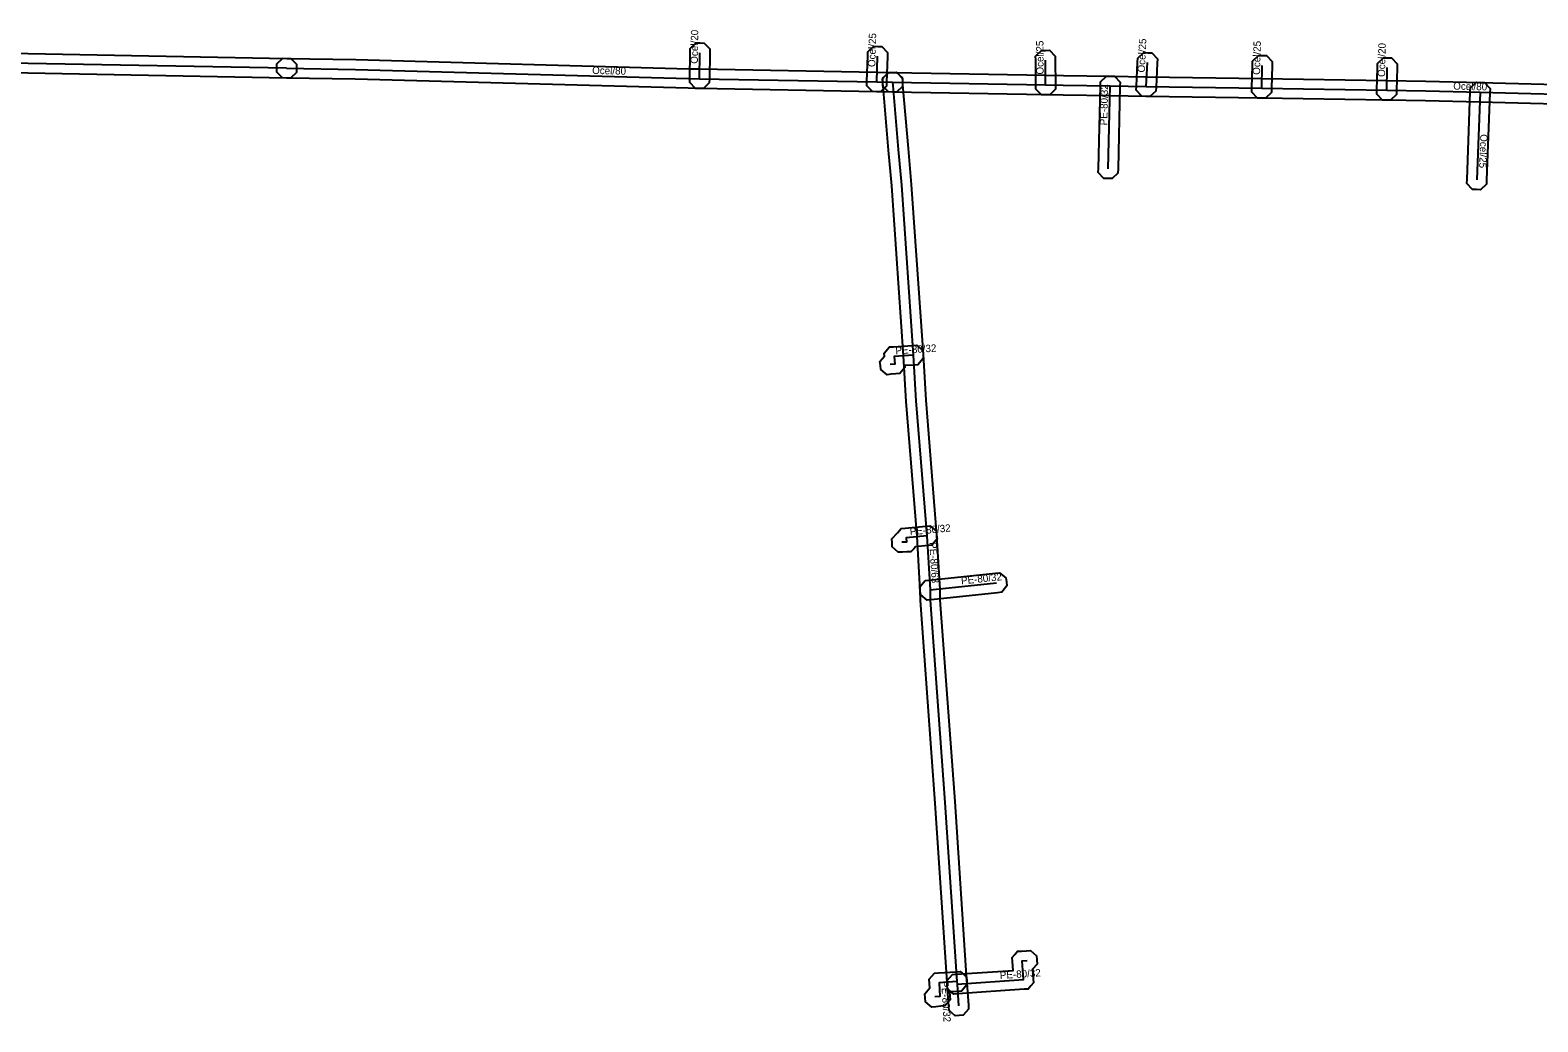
# Model space of a CAD drawing. Extents: x -569373 to -565022, y -1135090 to -1131496.
# Drawn here: x -565577.8 to -565424.2, y -1133558 to -1133457 of the extents above; entities that cross this region are included whole.
import ezdxf

# ---------------------------------------------------------------- set-up
doc = ezdxf.new("R2010")
doc.units = 0
for name, color, linetype in [('1', 7, 'Continuous'), ('24', 7, 'Continuous'), ('30', 7, 'Continuous')]:
    doc.layers.add(name, color=color, linetype=linetype)

msp = doc.modelspace()

# ---------------------------------------------------------------- linework, layer by layer
at = {"layer": '1'}
for points in [[(-565551.275, -1133461.887), (-565551.689, -1133461.88), (-565578.038, -1133461.39), (-565632.147, -1133460.49), (-565632.561, -1133460.483), (-565633.137, -1133459.887), (-565633.13, -1133459.473), (-565633.123, -1133459.059), (-565632.527, -1133458.483), (-565632.113, -1133458.49), (-565578.002, -1133459.39), (-565551.651, -1133459.88), (-565551.237, -1133459.888), (-565550.663, -1133460.485), (-565550.67, -1133460.899), (-565550.678, -1133461.313)], [(-565510.596, -1133462.349), (-565510.59, -1133461.935), (-565510.55, -1133459.295), (-565510.544, -1133458.881), (-565509.949, -1133458.304), (-565509.535, -1133458.31), (-565509.121, -1133458.316), (-565508.544, -1133458.911), (-565508.55, -1133459.325), (-565508.59, -1133461.965), (-565508.596, -1133462.379), (-565509.191, -1133462.956), (-565509.605, -1133462.95), (-565510.019, -1133462.944)], [(-565492.542, -1133462.663), (-565492.53, -1133462.249), (-565492.45, -1133459.629), (-565492.437, -1133459.215), (-565491.833, -1133458.648), (-565491.419, -1133458.66), (-565491.005, -1133458.673), (-565490.438, -1133459.277), (-565490.45, -1133459.691), (-565490.53, -1133462.311), (-565490.543, -1133462.725), (-565491.147, -1133463.292), (-565491.561, -1133463.28), (-565491.975, -1133463.267)], [(-565475.328, -1133463.008), (-565475.33, -1133462.594), (-565475.34, -1133460.064), (-565475.342, -1133459.65), (-565474.758, -1133459.062), (-565474.344, -1133459.06), (-565473.93, -1133459.058), (-565473.342, -1133459.642), (-565473.34, -1133460.056), (-565473.33, -1133462.586), (-565473.328, -1133463), (-565473.912, -1133463.588), (-565474.326, -1133463.59), (-565474.74, -1133463.592)], [(-565465.088, -1133463.119), (-565465.069, -1133462.705), (-565464.959, -1133460.265), (-565464.94, -1133459.851), (-565464.329, -1133459.292), (-565463.915, -1133459.311), (-565463.501, -1133459.33), (-565462.942, -1133459.941), (-565462.961, -1133460.355), (-565463.071, -1133462.795), (-565463.09, -1133463.209), (-565463.701, -1133463.768), (-565464.115, -1133463.749), (-565464.529, -1133463.73)], [(-565552.067, -1133459.873), (-565551.653, -1133459.88), (-565544.628, -1133460), (-565510.697, -1133460.93), (-565509.572, -1133460.95), (-565491.512, -1133461.28), (-565489.901, -1133461.31), (-565489.487, -1133461.318), (-565488.913, -1133461.915), (-565488.92, -1133462.329), (-565488.928, -1133462.743), (-565489.525, -1133463.317), (-565489.939, -1133463.31), (-565491.548, -1133463.28), (-565509.608, -1133462.95), (-565510.743, -1133462.93), (-565544.672, -1133462), (-565551.687, -1133461.88), (-565552.101, -1133461.873), (-565552.677, -1133461.277), (-565552.67, -1133460.863), (-565552.663, -1133460.449)], [(-565453.32, -1133463.318), (-565453.31, -1133462.904), (-565453.25, -1133460.564), (-565453.239, -1133460.15), (-565452.638, -1133459.58), (-565452.224, -1133459.59), (-565451.81, -1133459.601), (-565451.24, -1133460.202), (-565451.25, -1133460.616), (-565451.31, -1133462.956), (-565451.321, -1133463.37), (-565451.922, -1133463.94), (-565452.336, -1133463.93), (-565452.75, -1133463.919)], [(-565440.579, -1133463.522), (-565440.57, -1133463.108), (-565440.52, -1133460.798), (-565440.511, -1133460.384), (-565439.912, -1133459.811), (-565439.498, -1133459.82), (-565439.084, -1133459.829), (-565438.511, -1133460.428), (-565438.52, -1133460.842), (-565438.57, -1133463.152), (-565438.579, -1133463.566), (-565439.178, -1133464.139), (-565439.592, -1133464.13), (-565440.006, -1133464.121)], [(-565488.946, -1133461.838), (-565488.922, -1133462.251), (-565488.903, -1133462.578), (-565488.344, -1133469.062), (-565488.013, -1133472.721), (-565486.822, -1133490.056), (-565486.542, -1133494.7), (-565485.432, -1133508.45), (-565485.1, -1133513.995), (-565485.09, -1133515.039), (-565483.592, -1133535.6), (-565482.373, -1133553.857), (-565482.353, -1133554.106), (-565482.202, -1133556.322), (-565482.174, -1133556.735), (-565482.719, -1133557.36), (-565483.132, -1133557.388), (-565483.545, -1133557.416), (-565484.17, -1133556.871), (-565484.198, -1133556.458), (-565484.347, -1133554.254), (-565484.367, -1133554.003), (-565485.588, -1133535.74), (-565487.09, -1133515.121), (-565487.1, -1133514.065), (-565487.428, -1133508.59), (-565488.538, -1133494.84), (-565488.818, -1133490.184), (-565490.007, -1133472.879), (-565490.336, -1133469.238), (-565490.897, -1133462.722), (-565490.918, -1133462.369), (-565490.942, -1133461.955), (-565490.392, -1133461.336), (-565489.979, -1133461.312), (-565489.565, -1133461.288)], [(-565468.96, -1133471.51), (-565468.95, -1133471.096), (-565468.75, -1133462.666), (-565468.74, -1133462.252), (-565468.14, -1133461.68), (-565467.726, -1133461.69), (-565467.312, -1133461.7), (-565466.74, -1133462.3), (-565466.75, -1133462.714), (-565466.95, -1133471.144), (-565466.96, -1133471.558), (-565467.56, -1133472.13), (-565467.974, -1133472.12), (-565468.388, -1133472.11)], [(-565429.046, -1133462.953), (-565429.061, -1133463.367), (-565429.391, -1133472.287), (-565429.406, -1133472.701), (-565430.013, -1133473.264), (-565430.427, -1133473.249), (-565430.841, -1133473.234), (-565431.404, -1133472.627), (-565431.389, -1133472.213), (-565431.059, -1133463.293), (-565431.044, -1133462.879), (-565430.437, -1133462.316), (-565430.023, -1133462.331), (-565429.609, -1133462.346)], [(-565491.208, -1133490.764), (-565490.755, -1133490.203), (-565490.775, -1133489.902), (-565490.23, -1133489.28), (-565489.817, -1133489.252), (-565487.887, -1133489.122), (-565487.474, -1133489.094), (-565486.85, -1133489.64), (-565486.822, -1133490.053), (-565486.794, -1133490.466), (-565487.34, -1133491.09), (-565487.753, -1133491.118), (-565488.687, -1133491.181), (-565488.676, -1133491.357), (-565489.194, -1133491.972), (-565489.594, -1133492.014), (-565490.064, -1133492.064), (-565490.476, -1133492.108), (-565491.121, -1133491.588), (-565491.164, -1133491.176)], [(-565489.427, -1133508.199), (-565489.41, -1133508.198), (-565489.039, -1133507.762), (-565488.634, -1133507.724), (-565486.524, -1133507.524), (-565486.112, -1133507.485), (-565485.473, -1133508.013), (-565485.434, -1133508.426), (-565485.395, -1133508.838), (-565485.923, -1133509.477), (-565486.336, -1133509.516), (-565487.594, -1133509.635), (-565487.765, -1133509.827), (-565488.046, -1133510.141), (-565488.467, -1133510.159), (-565488.927, -1133510.179), (-565489.341, -1133510.197), (-565489.951, -1133509.637), (-565489.969, -1133509.223), (-565489.987, -1133508.809)], [(-565486.616, -1133513.078), (-565486.204, -1133513.035), (-565479.424, -1133512.325), (-565479.012, -1133512.282), (-565478.368, -1133512.804), (-565478.325, -1133513.216), (-565478.282, -1133513.628), (-565478.804, -1133514.272), (-565479.216, -1133514.315), (-565485.996, -1133515.025), (-565486.408, -1133515.068), (-565487.052, -1133514.546), (-565487.095, -1133514.134), (-565487.138, -1133513.722)], [(-565475.197, -1133552.142), (-565475.65, -1133552.655), (-565475.582, -1133553.652), (-565475.554, -1133554.065), (-565475.826, -1133554.377), (-565476.099, -1133554.69), (-565476.512, -1133554.718), (-565483.282, -1133555.178), (-565483.695, -1133555.206), (-565484.32, -1133554.661), (-565484.348, -1133554.248), (-565484.376, -1133553.835), (-565483.831, -1133553.21), (-565483.418, -1133553.182), (-565477.646, -1133552.79), (-565477.708, -1133551.888), (-565477.736, -1133551.473), (-565477.461, -1133551.16), (-565477.187, -1133550.847), (-565476.771, -1133550.822), (-565476.281, -1133550.792), (-565475.868, -1133550.767), (-565475.247, -1133551.316), (-565475.222, -1133551.729)], [(-565486.645, -1133555.173), (-565486.142, -1133554.563), (-565486.168, -1133554.107), (-565486.192, -1133553.696), (-565485.647, -1133553.079), (-565485.237, -1133553.052), (-565483.437, -1133552.932), (-565483.024, -1133552.905), (-565482.4, -1133553.45), (-565482.372, -1133553.863), (-565482.345, -1133554.276), (-565482.89, -1133554.9), (-565483.303, -1133554.928), (-565484.115, -1133554.982), (-565484.092, -1133555.383), (-565484.069, -1133555.785), (-565484.593, -1133556.396), (-565484.994, -1133556.435), (-565485.514, -1133556.485), (-565485.927, -1133556.525), (-565486.566, -1133555.998), (-565486.605, -1133555.586)]]:
    msp.add_lwpolyline(points, close=True, dxfattribs=at)
msp.add_lwpolyline([(-565417.126, -1133464.67), (-565430.086, -1133464.33), (-565435.61, -1133464.19), (-565439.585, -1133464.13), (-565452.326, -1133463.93), (-565464.086, -1133463.75), (-565467.765, -1133463.69), (-565472.546, -1133463.62), (-565474.347, -1133463.59), (-565489.938, -1133463.31), (-565490.352, -1133463.303), (-565490.927, -1133462.706), (-565490.92, -1133462.292), (-565490.913, -1133461.878), (-565490.316, -1133461.303), (-565489.902, -1133461.31), (-565474.313, -1133461.59), (-565472.514, -1133461.62), (-565467.735, -1133461.69), (-565464.054, -1133461.75), (-565452.294, -1133461.93), (-565439.555, -1133462.13), (-565435.57, -1133462.19), (-565430.034, -1133462.33), (-565417.074, -1133462.67)], dxfattribs=at)
at = {"layer": '24'}
for points in [[(-565551.67, -1133460.88), (-565578.02, -1133460.39), (-565632.13, -1133459.49)], [(-565509.59, -1133461.95), (-565509.55, -1133459.31)], [(-565551.67, -1133460.88), (-565544.65, -1133461), (-565510.72, -1133461.93), (-565509.59, -1133461.95), (-565491.53, -1133462.28), (-565489.92, -1133462.31)], [(-565491.53, -1133462.28), (-565491.45, -1133459.66)], [(-565474.33, -1133462.59), (-565474.34, -1133460.06)], [(-565464.07, -1133462.75), (-565463.96, -1133460.31)], [(-565452.31, -1133462.93), (-565452.25, -1133460.59)], [(-565439.57, -1133463.13), (-565439.52, -1133460.82)], [(-565489.92, -1133462.31), (-565489.9, -1133462.65), (-565489.34, -1133469.15), (-565489.01, -1133472.8), (-565487.82, -1133490.12), (-565487.54, -1133494.77), (-565486.43, -1133508.52), (-565486.1, -1133514.03), (-565486.09, -1133515.08), (-565484.59, -1133535.67), (-565483.37, -1133553.93), (-565483.35, -1133554.18), (-565483.2, -1133556.39)], [(-565489.92, -1133462.31), (-565474.33, -1133462.59), (-565472.53, -1133462.62), (-565467.75, -1133462.69), (-565464.07, -1133462.75), (-565452.31, -1133462.93), (-565439.57, -1133463.13), (-565435.59, -1133463.19), (-565430.06, -1133463.33), (-565417.1, -1133463.67), (-565409.9, -1133463.86), (-565397.36, -1133464.19), (-565393.74, -1133464.22), (-565377.89, -1133464.35), (-565376.401, -1133463.519)], [(-565467.95, -1133471.12), (-565467.75, -1133462.69)], [(-565430.06, -1133463.33), (-565430.39, -1133472.25)], [(-565487.82, -1133490.12), (-565489.75, -1133490.25), (-565489.7, -1133491.02), (-565490.17, -1133491.07)], [(-565486.43, -1133508.52), (-565488.54, -1133508.72), (-565488.51, -1133509.16), (-565488.97, -1133509.18)], [(-565486.1, -1133514.03), (-565479.32, -1133513.32)], [(-565483.35, -1133554.18), (-565476.58, -1133553.72), (-565476.71, -1133551.82), (-565476.22, -1133551.79)], [(-565483.37, -1133553.93), (-565485.17, -1133554.05), (-565485.09, -1133555.44), (-565485.61, -1133555.49)]]:
    msp.add_lwpolyline(points, dxfattribs=at)

# ---------------------------------------------------------------- texts
at = {"layer": '30'}
for s, rotation, p in [('Ocel/20', 89.13195, (-565509.77, -1133460.43)), ('Ocel/25', 88.25105, (-565491.69, -1133460.77)), ('Ocel/25', 87.41874, (-565464.215, -1133461.33)), ('Ocel/25', 90.22646, (-565474.535, -1133461.525)), ('Ocel/25', 88.5312, (-565452.48, -1133461.56)), ('Ocel/20', 88.76003, (-565439.745, -1133461.775)), ('Ocel/80', 358.42995, (-565520.546, -1133461.455)), ('PE-80/32', 88.64092, (-565468.05, -1133466.705)), ('Ocel/80', 358.54978, (-565432.8, -1133463.056)), ('Ocel/25', 267.88128, (-565430.025, -1133467.59)), ('PE-80/32', 3.85348, (-565489.606, -1133490.027)), ('PE-80/32', 5.4147, (-565488.134, -1133508.463)), ('PE-80/63', 273.42741, (-565486.178, -1133509.187)), ('PE-80/32', 5.97821, (-565482.91, -1133513.475)), ('PE-80/32', 3.88709, (-565478.97, -1133553.669)), ('PE-80/32', 273.29396, (-565484.967, -1133553.905))]:
    msp.add_text(s, height=0.75, rotation=rotation, dxfattribs=at).set_placement(p)

doc.saveas('drawing.dxf')
